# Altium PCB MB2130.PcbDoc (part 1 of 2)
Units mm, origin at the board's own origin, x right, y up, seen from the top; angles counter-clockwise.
Board outline 43 x 51.11 mm, 4 copper layers (Top Layer, Signal Layer 1, Signal Layer 2, Bottom Layer), stack 1.592 mm thick; 94 components, 90 nets, 382 pads, 433 vias.
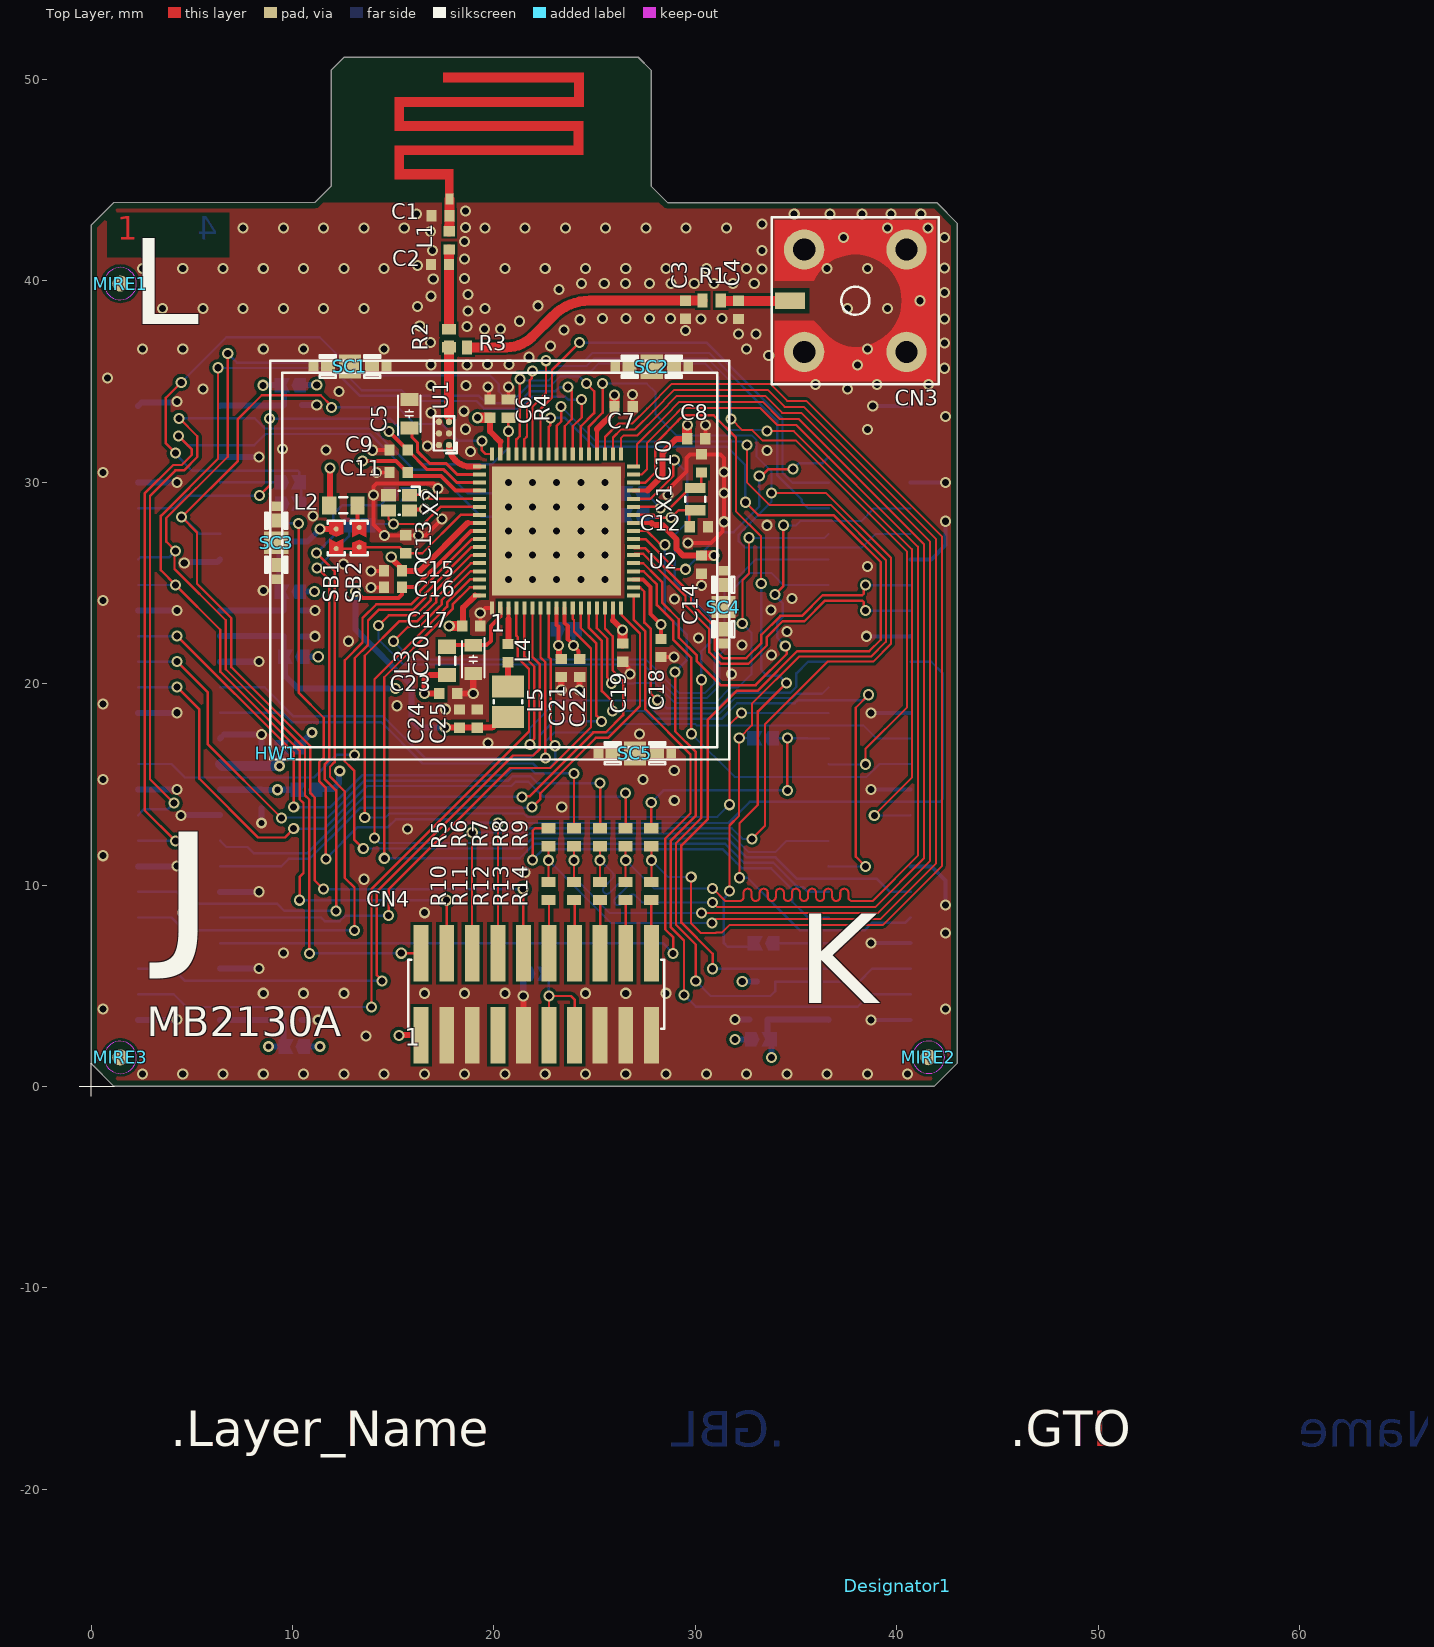
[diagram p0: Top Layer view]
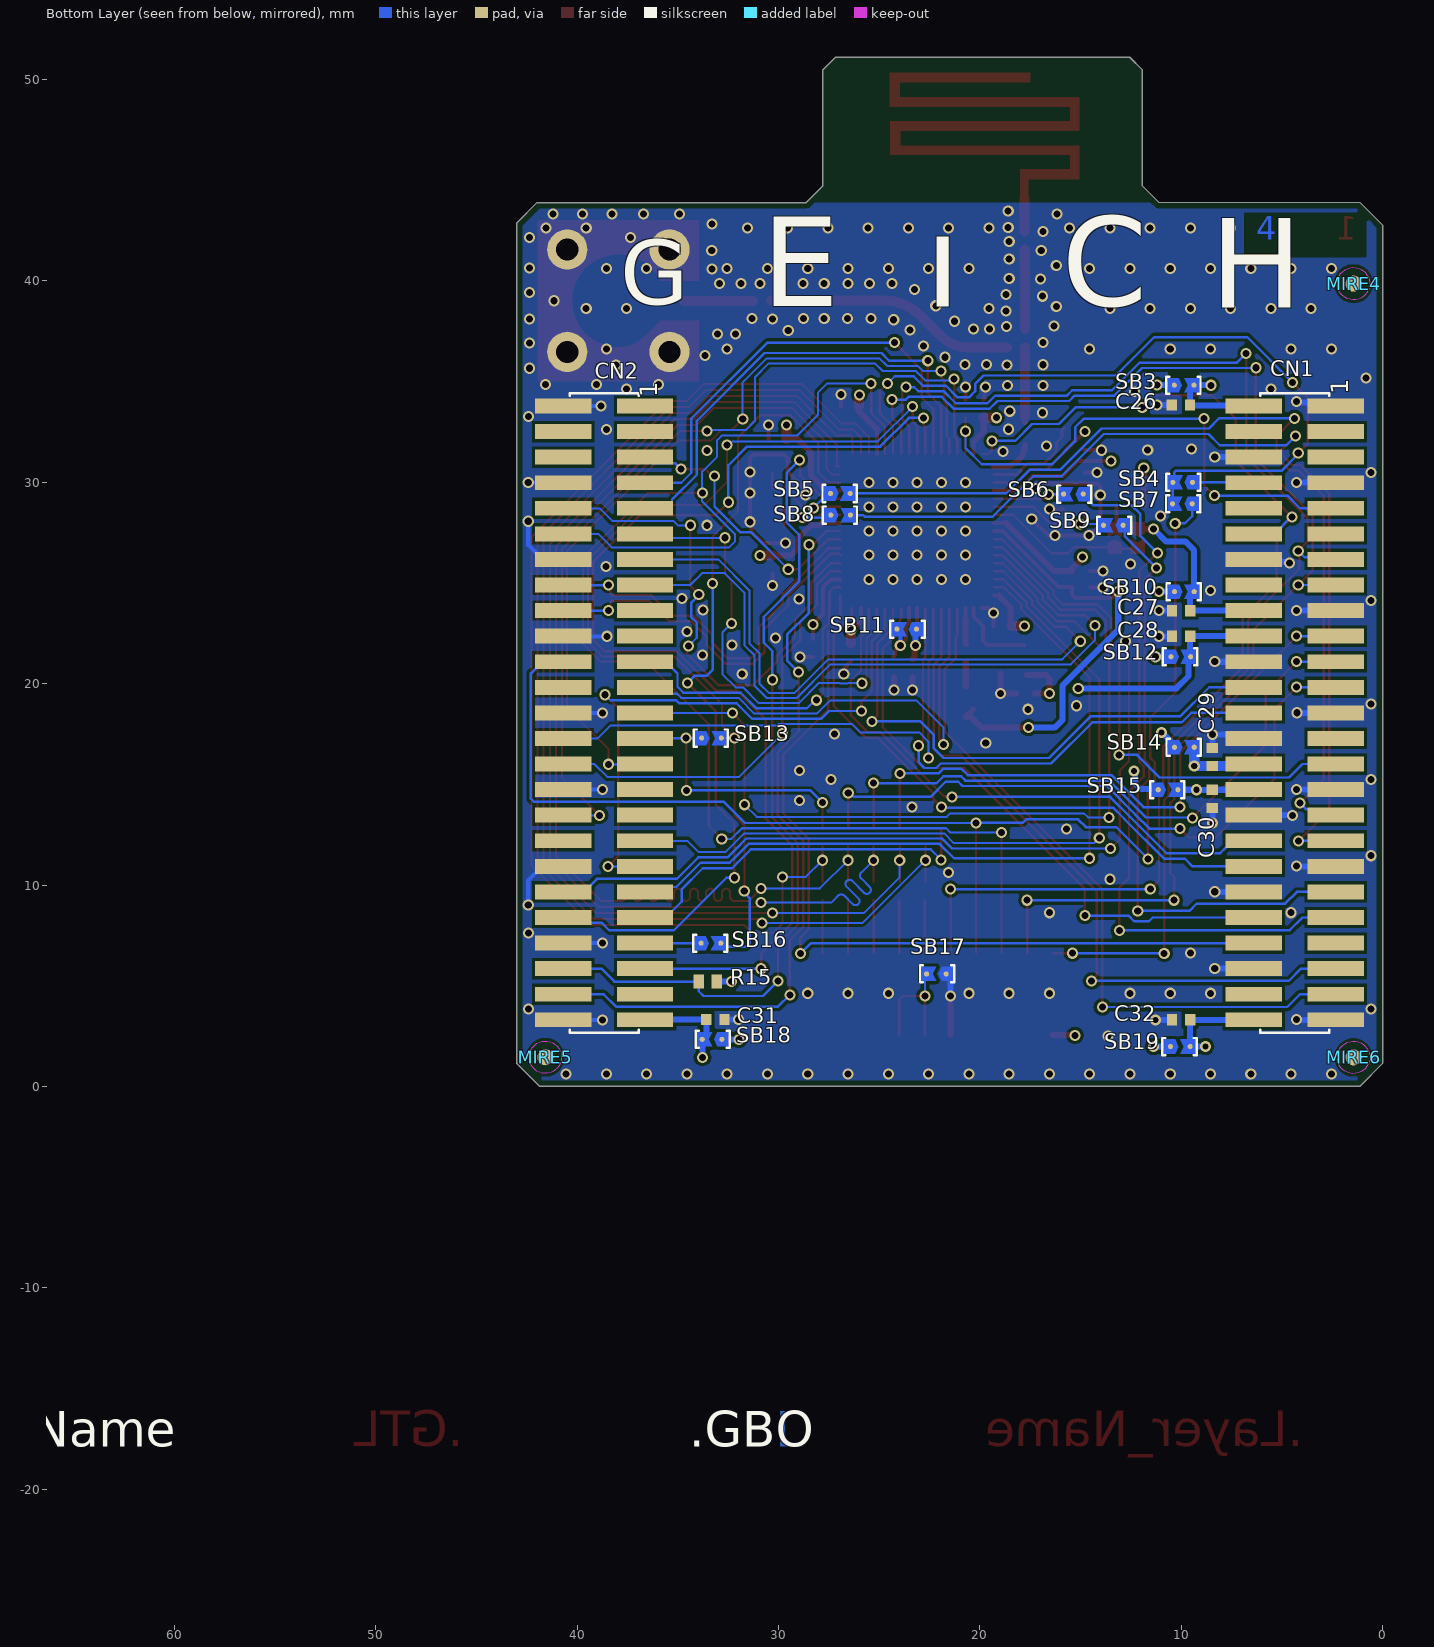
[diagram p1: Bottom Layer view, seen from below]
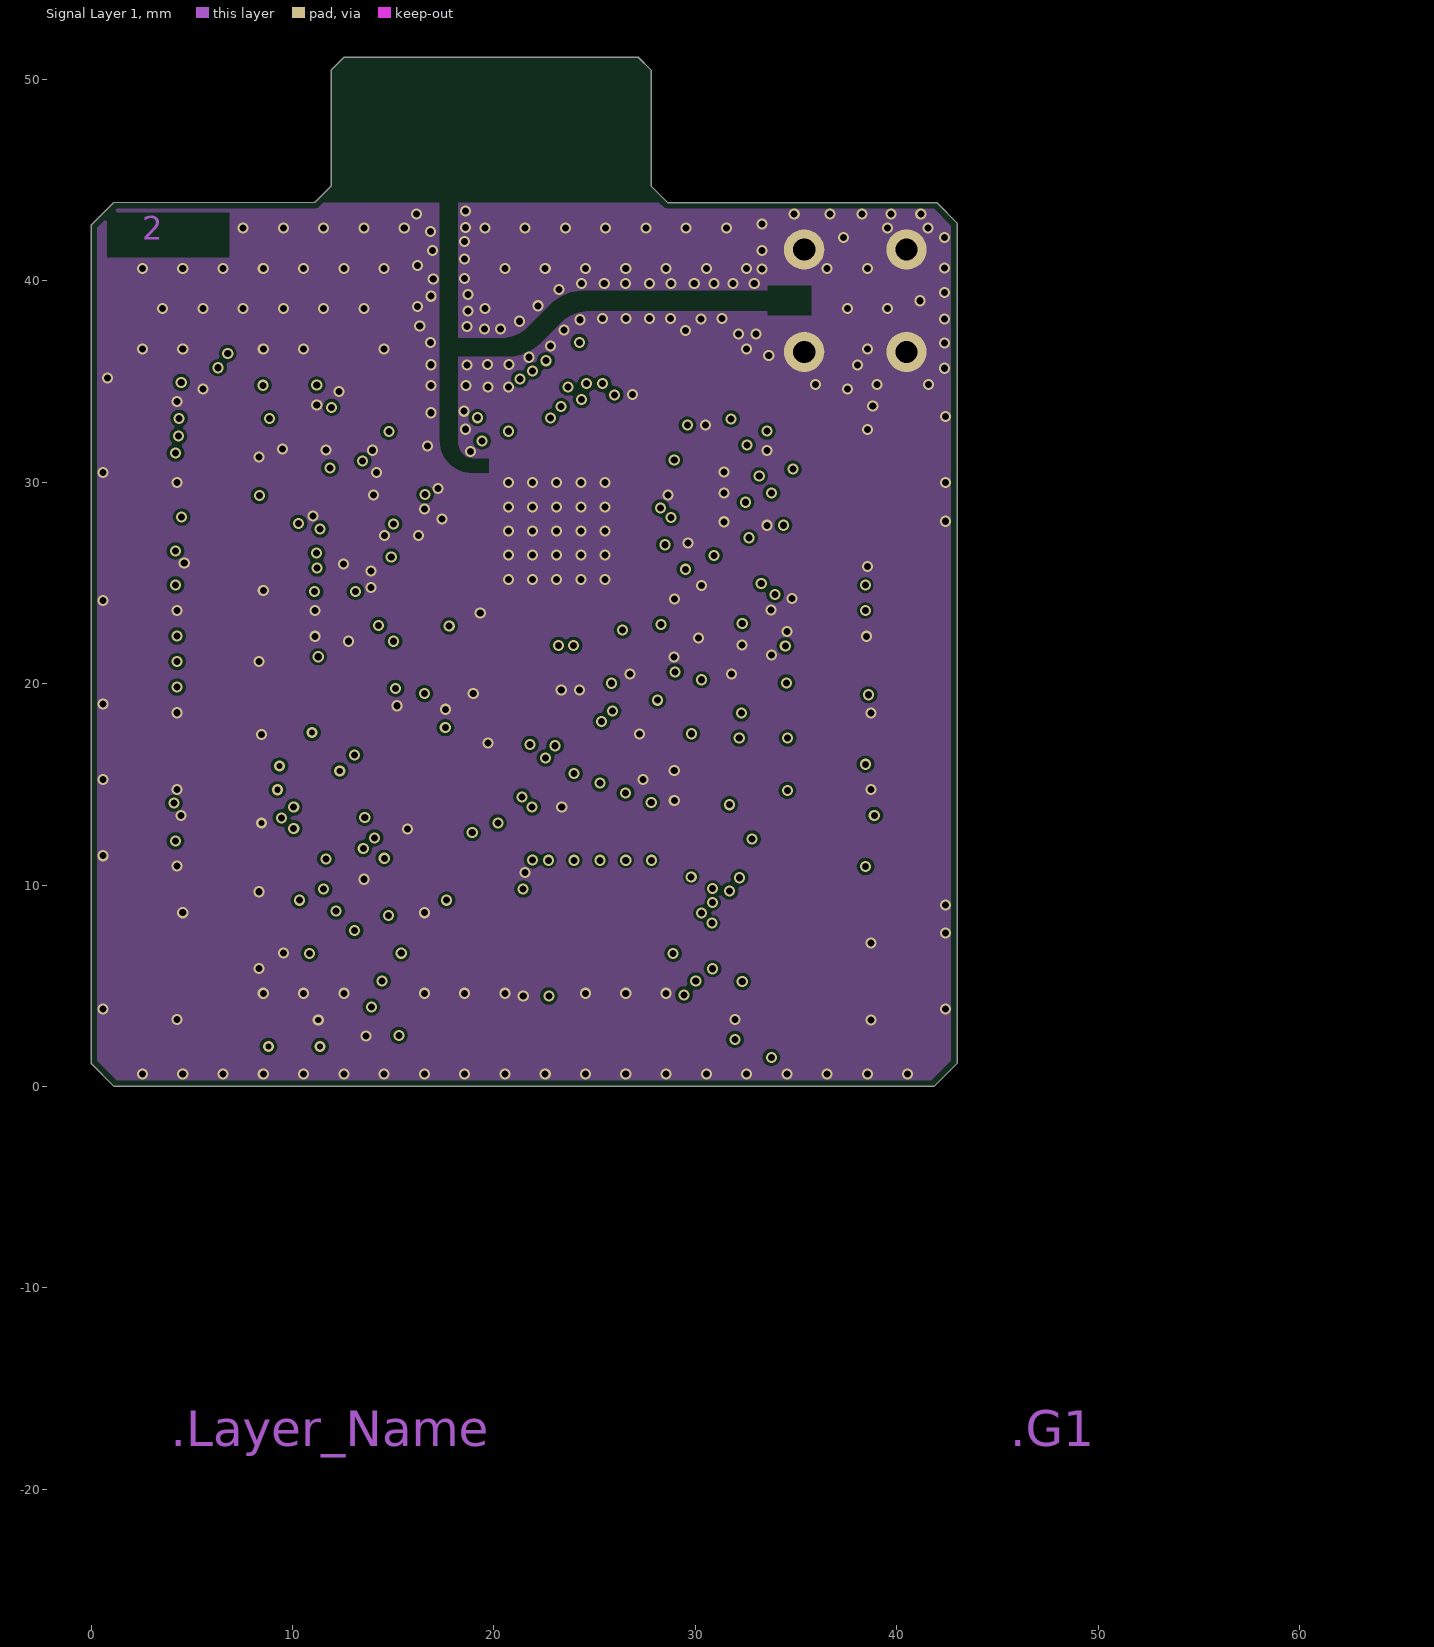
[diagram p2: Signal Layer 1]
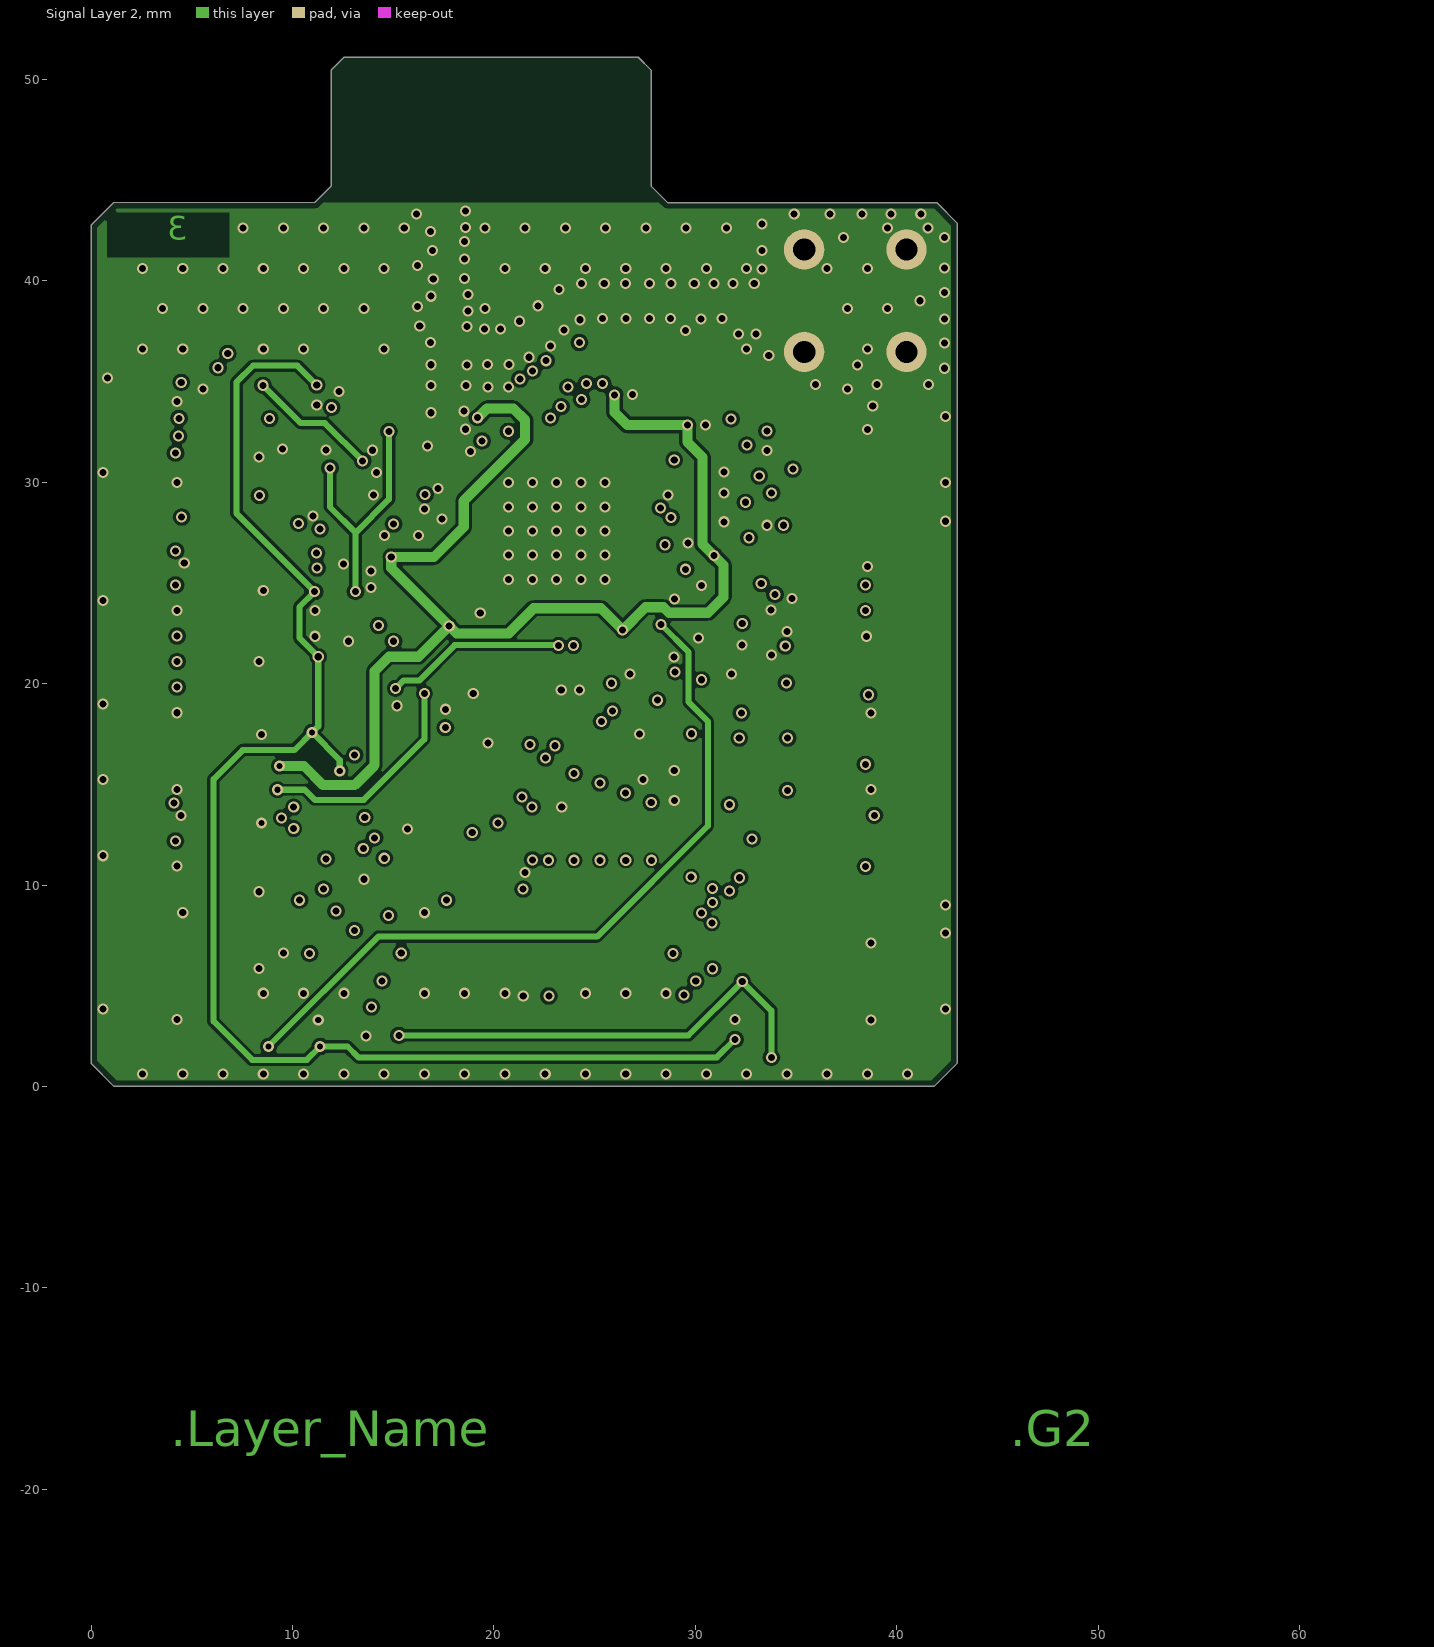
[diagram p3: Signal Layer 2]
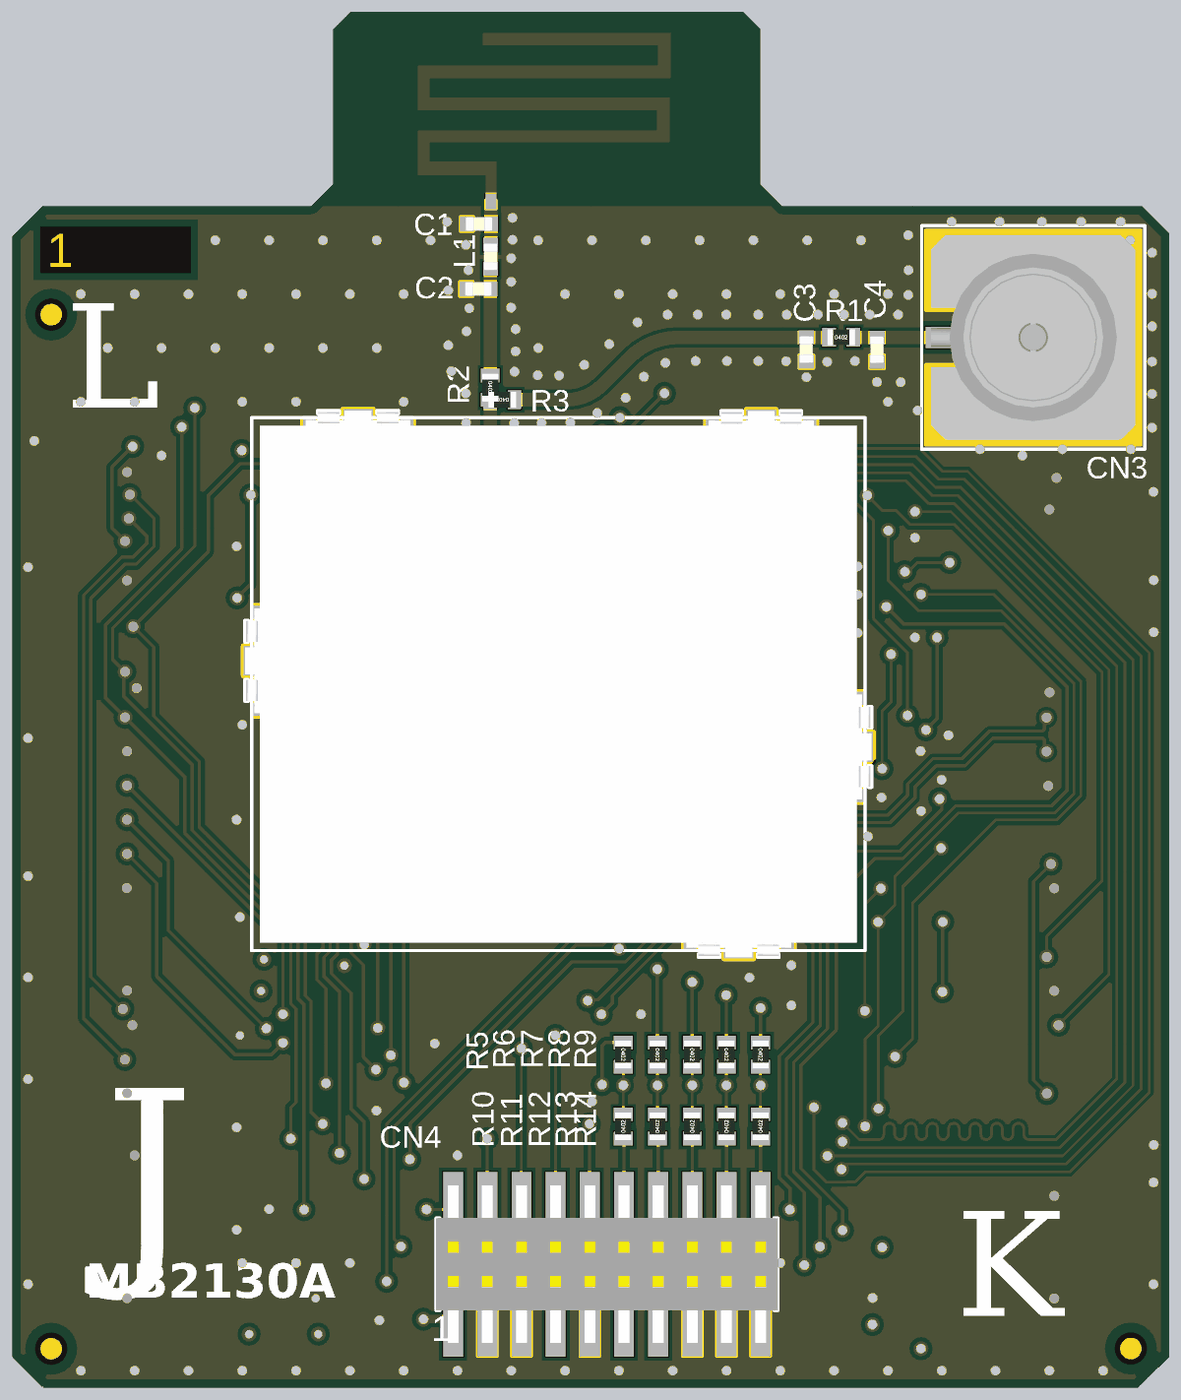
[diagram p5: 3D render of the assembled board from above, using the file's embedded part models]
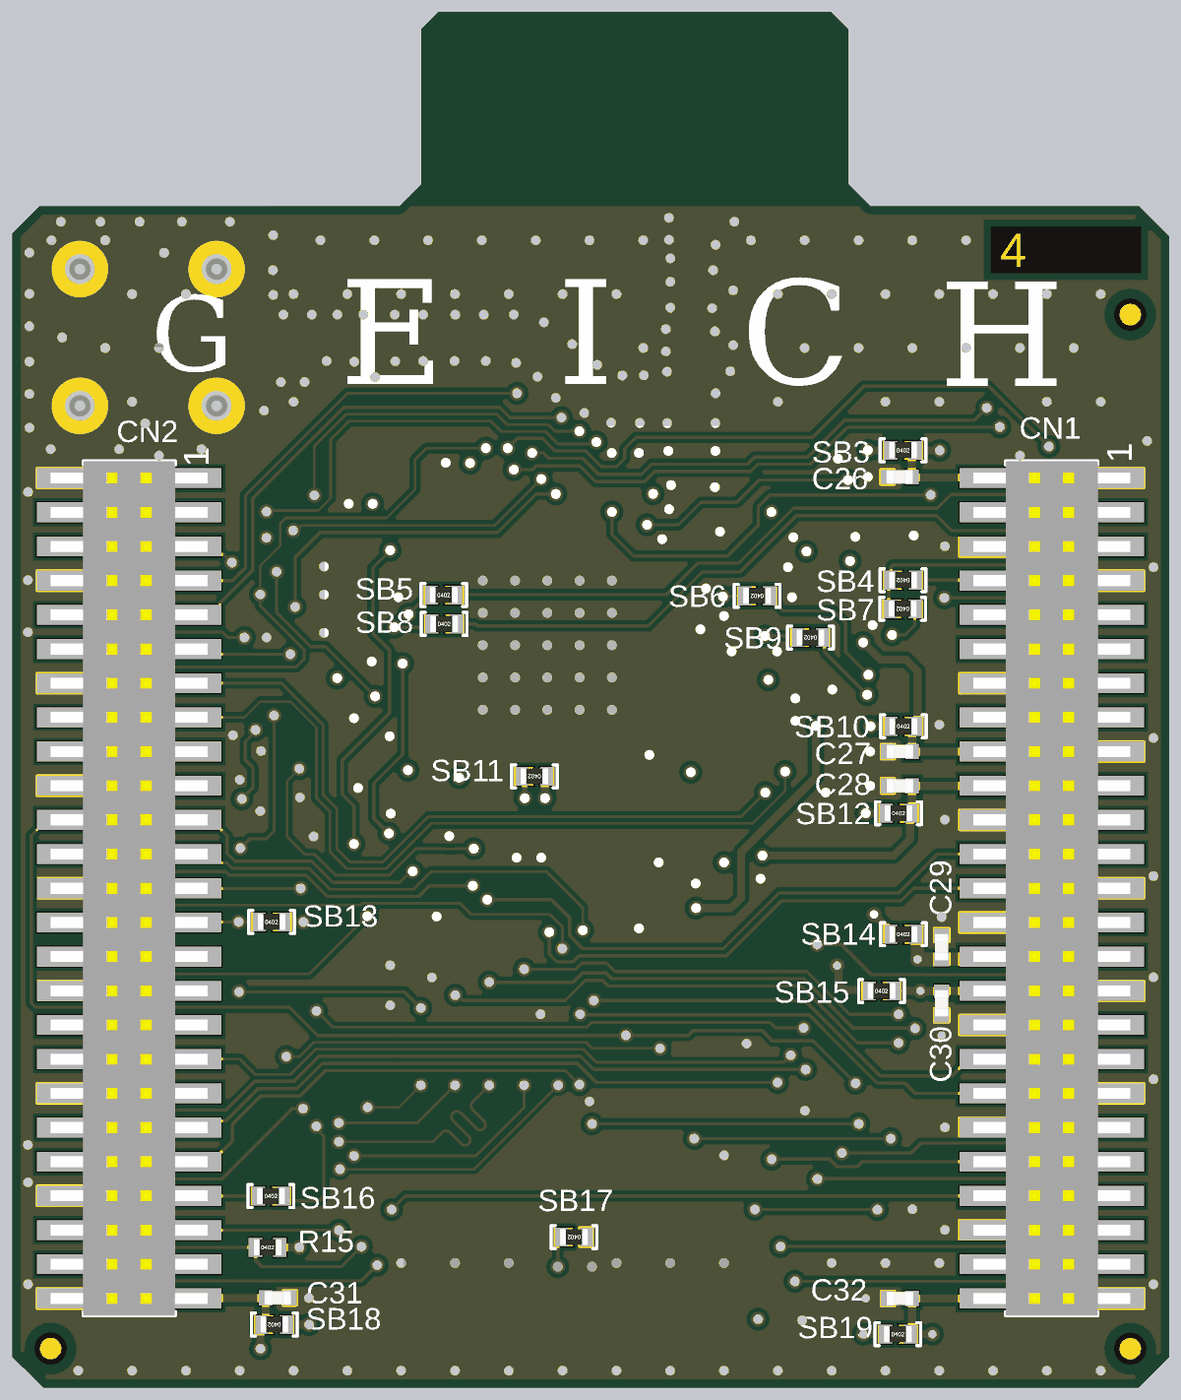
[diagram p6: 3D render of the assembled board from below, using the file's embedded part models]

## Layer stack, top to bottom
Top Solder: solder mask 0.02, Solder Resist, Dk 3.5
Top Layer: signal copper 0.07
Dielectric 1: prepreg 0.076, 1080HR RC68, Dk 4.2
Signal Layer 1: signal copper 0.035
Dielectric 2: core 1.23, FR4, Dk 4.5
Signal Layer 2: signal copper 0.035
Dielectric 3: prepreg 0.076, 1080HR RC68, Dk 4.2
Bottom Layer: signal copper 0.07
Bottom Solder: solder mask 0.02, Solder Resist, Dk 3.5

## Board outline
0,1.139 0,42.769 1.122,43.891 11.106,43.893 11.927,44.713 11.927,50.471 12.562,51.106 27.167,51.106 27.802,50.471 27.802,44.711 28.622,43.891 41.987,43.886 43,42.873 43.001,1.141 41.852,0 1.139,0

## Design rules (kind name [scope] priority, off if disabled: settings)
BoardOutlineClearance [All] p1: gap=0.3 ignorepadtopadclearanceinfootprint=FALSE except(0: Arc-SplitContinuation Track-SplitContinuation SMDPad-SplitContinuation THPad-SplitContinuation Via-SplitContinuation Fill-SplitContinuation Poly-SplitContinuation Region-SplitContinuation Text-SplitContinuation)
Clearance Clearance_DP_GND [InNetClass('DP') vs InNet('GND')] p1: gap=0.12 ignorepadtopadclearanceinfootprint=FALSE
Clearance Clearance_RF-IN_GND [InNet('IPD_in') vs InNet('GND')] p2: gap=0.15 ignorepadtopadclearanceinfootprint=FALSE
Clearance Clearance_SE_GND [InNetClass('S50') vs InNet('GND')] p3: gap=0.12 ignorepadtopadclearanceinfootprint=FALSE
Clearance Clearance_S50 [InNetClass('S50')] p4: gap=0.15 ignorepadtopadclearanceinfootprint=FALSE except(0.2: Arc-Arc Arc-Track Arc-Fill Arc-Poly Arc-Region Track-Track Track-Fill Track-Poly Track-Region)
Clearance [All] p5: gap=0.15 ignorepadtopadclearanceinfootprint=FALSE
ComponentClearance [All] p1: gap=0.2 collisioncheckmode=3 verticalgap=0.2 showdistances=FALSE
DiffPairsRouting [All] p1: maxlimit=0.254 minlimit=0.15 mostfreqgap=0.254 toplayer_maxgap=0.15 toplayer_prefgap=0.15 toplayer_minwidth=0.12 toplayer_maxwidth=0.12 toplayer_prefwidth=0.12 bottomlayer_maxgap=0.15 bottomlayer_prefgap=0.15 bottomlayer_minwidth=0.12 bottomlayer_maxwidth=0.12 bottomlayer_prefwidth=0.12 impedanceprofiledriven=TRUE impedanceprofileid={83C80AEC-0C39-4BC7-B724-3D17928A45DD} impedanceprofilevalue=90.000000 maxuncoupledlength=12.7
HoleSize [All] p1: absolutevalues=TRUE maxlimit=10 minlimit=0.025 maxpercent=80.000 minpercent=20.000
MatchedLengths MatchedLengths_ETM [InNetClass('ETM')] p1: tolerance=3 checknetsindiffpair=FALSE checkdiffpairvsdiffpair=TRUE checkxsignals=TRUE checkothers=TRUE
MinimumSolderMaskSliver [All] p1: minsoldermaskwidth=0.1
PlaneConnect [All] p1: planeconnectstyle=Relief reliefexpansion=0.508 reliefentries=4 reliefconductorwidth=0.21 reliefairgap=0.21
PolygonConnect Path_RF [InNet('NetC12_2')] p1: connectstyle=Direct reliefconductorwidth=0.254 reliefentries=4 polygonreliefangle="90 Angle" airgapwidth=0.254
PolygonConnect PolygonConnect_via [IsVia] p2: connectstyle=Direct reliefconductorwidth=0.254 reliefentries=4 polygonreliefangle="90 Angle" airgapwidth=0.254
PolygonConnect General [All] p3: connectstyle=Direct reliefconductorwidth=0.2 reliefentries=4 polygonreliefangle="90 Angle" airgapwidth=0.2
RoutingVias [All] p1: holewidth=0.3 width=0.8 viastyle="Through Hole" minholewidth=0.2 minwidth=0.5 maxholewidth=3.5 maxwidth=6.5
SilkToSilkClearance [All] p1 off: silktosilkclearance=0.2
SilkToSolderMaskClearance [IsPad] p1 off: minsilkscreentomaskgap=0.2 clearancetoexposedcopper=TRUE
SolderMaskExpansion [All] p1: expansion=0.102 istentingtop=FALSE
Width Width_VDD [InNetClass('VDD')] p1: maxlimit=0.3 minlimit=0.2 preferedwidth=0.3
Width Width_VDD4 [InNet('VDD4')] p2: maxlimit=0.5 minlimit=0.2 preferedwidth=0.5
Width Width_S50 [InNetClass('S50')] p3: maxlimit=0.5 minlimit=0.1 preferedwidth=0.254 toplayer_prefwidth=0.1 bottomlayer_prefwidth=0.1 impedanceprofiledriven=TRUE impedanceprofileid={8D9B8D96-6614-473A-BC45-880F726FB23A} impedanceprofilevalue=50.000000 minimp=50.000000 maximp=50.000000 favimp=50.000000
Width [All] p4: maxlimit=6 minlimit=0.1 preferedwidth=0.12 midlayer1_maxwidth=0.512 midlayer2_maxwidth=0.512 minimp=50.000000 maximp=50.000000 favimp=50.000000
23 further rules are at their usual default settings.

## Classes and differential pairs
net class DP: USB_HS_N USB_HS_P
net class VDD: GND NetSB3_1 VDD1 VDD3 VDD5 VDD14 VDDA VDDUSB
net class ETM: ETM.CLK ETM.D0 ETM.D1 ETM.D2 ETM.D3
net class S50: ant_in ant_path ETM.CLK ETM.D0 ETM.D1 ETM.D2 ETM.D3 IPD_out SMA-path SMA_in
component class U_MCU_Clock&Reset: C10 C12 R4 X1 X2
component class U_External_Debug_Interface: CN4 J1 R10 R11 R12 R13 R14 SB17
component class U_MCU: C26 C27 C28 C29 C30 C31 C32 CN1 CN2 R5 R6 R7 R8 R9 R15 SB3 SB4 SB5 SB6 SB7 SB8 SB9 SB10 SB12 SB13 SB14 SB15 SB16 SB18 SB19
component class U_MCU_Power: ANT1 C1 C2 C3 C4 C5 C6 C7 C8 C9 C11 C13 C14 C15 C16 C17 C18 C19 C20 C21 C22 C23 C24 C25 CN3 HW1 L1 L2 L3 L4 L5 R1 R2 R3 SB1 SB2 SB11 SC1 SC2 SC3 SC4 SC5 U1 U2
differential pair USB: +USB_HS_P -USB_HS_N

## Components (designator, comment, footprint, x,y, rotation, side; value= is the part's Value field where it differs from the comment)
ANT1 "2.4GHz_BT_ANT" ANT_BT_BNRG_2P4GHZ_MB2032 17.649,44.066 r90 top value=2.4GHZ_BNRG_ANT
C1 "Capacitor" C0402 17.348,43.231 r0 top value=1.1pF
C2 "Capacitor" C0402 17.323,40.818 r180 top value=1.5pF
C3 "Capacitor" C0402 29.515,38.567 r90 top value=1.5pF
C4 "Capacitor" C0402 32.14,38.56 r90 top value=1.8pF
C5 "Capacitor" C0603 15.799,33.402 r270 top value=470nF
C6 "Capacitor" C0402 19.807,33.655 r90 top value=100nF
C7 "Capacitor" C0402 26.441,33.757 r0 top value=100nF
C8 "Capacitor" C0402 30.048,32.156 r0 top value=100nF
C9 "Capacitor" C0402 15.265,31.598 r180 top value=100nF
C10 "Capacitor" C0402 30.302,30.937 r270 top value=6pF
C11 "Capacitor" C0402 15.265,30.48 r180 top value=100nF
C12 "Capacitor" C0402 30.175,27.788 r180 top value=6pF
C13 "Capacitor" C0402 15.621,26.924 r90 top value=100nF
C14 "Capacitor" C0402 30.302,25.908 r270 top value=100nF
C15 "Capacitor" C0402 14.986,25.603 r180 top value=100nF
C16 "Capacitor" C0402 14.986,24.79 r0 top value=100nF
C17 "Capacitor" C0402 18.872,22.86 r0 top value=100nF
C18 "Capacitor" C0402 28.296,21.768 r270 top value=100nF
C19 "Capacitor" C0402 26.391,21.539 r270 top value=100nF
C20 "Capacitor" C0603 18.974,21.209 r90 top value=10uF
C21 "Capacitor" C0402 23.343,20.777 r90 top value=1uF
C22 "Capacitor" C0402 24.257,20.777 r90 top value=1uF
C23 "Capacitor" C0402 17.729,19.507 r0 top value=1uF
C24 "Capacitor" C0402 18.288,18.263 r90 top value=2.2uF
C25 "Capacitor" C0402 19.177,18.263 r270 top value=4.7uF
C26 "Capacitor" C0402 10.019,33.832 r180 bottom value=1uF
C27 "Capacitor" C0402 10.007,23.627 r180 bottom value=1uF
C28 "Capacitor" C0402 10.008,22.352 r180 bottom value=1uF
C29 "Capacitor" C0402 8.458,16.358 r270 bottom value=1uF
C30 "Capacitor" C0402 8.458,14.275 r90 bottom value=1uF
C31 "Capacitor" C0402 33.135,3.327 r0 bottom value=1uF
C32 "Capacitor" C0402 10.008,3.306 r180 bottom value=1uF
CN1 "FTSH-125-02-L-DV" CON_SAMTEC_FTSH-125-02-L-DV_INV 4.366,18.548 r270 bottom locked value="Header 25x2"
CN2 "FTSH-125-02-L-DV" CON_SAMTEC_FTSH-125-02-L-DV_INV 38.656,18.548 r270 bottom locked value="Header 25x2"
CN3 "SMA-J-P-H-ST-EM1" CON_ROSENBERGER_32K141_40ML5 37.948,39.014 r270 top value=32K141-40ML5
CN4 "Header 10x2" CON_SAMTEC_FTSH-110-01-L-DV 22.101,4.579 r0 top
Designator1 "Comment" Sheetbox_4L2S -5.049,-30.142 r0 top
HW1 "RF Shield (22.2x19.2x2mm)" SHIELD_RF_ST-CUSTOM_22P2X19P2_H2 9.195,16.535 r0 top locked
L1 "Inductor" C0402 17.78,42.012 r90 top value=1.5nH
L2 "BEAD" IND_0603_H0P8 12.522,28.854 r180 top value="47R @ 100MHz"
L3 "BEAD" IND_0603_H0P8 17.678,21.133 r270 top value="47R @ 100MHz"
L4 "Inductor" C0402 20.701,21.514 r270 top value=10nH
L5 "Inductor" L0805_H0P9 20.701,19.101 r270 top value=2.2uH
MIRE1 "Comment" MIRE_PLACE_SMD_0P8MM 1.446,39.863 r0 top
MIRE2 "Comment" MIRE_PLACE_SMD_0P8MM 41.576,1.448 r0 top
MIRE3 "Comment" MIRE_PLACE_SMD_0P8MM 1.446,1.441 r0 top
MIRE4 "Comment" MIRE_PLACE_SMD_0P8MM 1.446,39.863 r180 bottom
MIRE5 "Comment" MIRE_PLACE_SMD_0P8MM 41.576,1.448 r180 bottom
MIRE6 "Comment" MIRE_PLACE_SMD_0P8MM 1.446,1.441 r180 bottom
"PCB SPEC1" "Comment" PCB_SPECIFICATIONS -2.994,71.413 r0 top
R1 "Resistor" R0402 30.81,39.024 r0 top value=0R
R2 "Resistor" R0402 17.765,37.151 r270 top value=0R
R3 "Resistor" R0402 18.215,36.701 r180 top value=0R
R4 "Resistor" R0402 20.722,33.655 r90 top value=100K
R5 "Resistor" R0402 22.708,12.37 r270 top value=0R
R6 "Resistor" R0402 23.978,12.37 r270 top value=0R
R7 "Resistor" R0402 25.273,12.37 r270 top value=0R
R8 "Resistor" R0402 26.543,12.37 r270 top value=0R
R9 "Resistor" R0402 27.813,12.37 r270 top value=0R
R10 "Resistor" R0402 22.708,9.703 r90 top value=0R
R11 "Resistor" R0402 23.978,9.703 r90 top value=0R
R12 "Resistor" R0402 25.273,9.703 r90 top value=0R
R13 "Resistor" R0402 26.543,9.703 r90 top value=0R
R14 "Resistor" R0402 27.813,9.703 r90 top value=0R
R15 "Resistor" R0402 33.51,5.207 r180 bottom value=100K
SB1 "SB_ON" SOLDER-BRIDGE_R0402-0R 12.167,27.229 r270 top
SB2 "SB_ON" SOLDER-BRIDGE_R0402-0R 13.31,27.229 r90 top
SB3 "SB_ON" SOLDER-BRIDGE_R0402-0R 9.892,34.823 r180 bottom
SB4 "SB_ON" SOLDER-BRIDGE_R0402-0R 9.892,29.997 r0 bottom
SB5 "SB_ON" SOLDER-BRIDGE_R0402-0R 26.964,29.442 r180 bottom
SB6 "SB_ON" SOLDER-BRIDGE_R0402-0R 15.316,29.413 r0 bottom
SB7 "SB_ON" SOLDER-BRIDGE_R0402-0R 9.906,28.931 r0 bottom
SB8 "SB_ON" SOLDER-BRIDGE_R0402-0R 26.949,28.372 r180 bottom
SB9 "SB_ON" SOLDER-BRIDGE_R0402-0R 13.335,27.864 r0 bottom
SB10 "SB_ON" SOLDER-BRIDGE_R0402-0R 9.88,24.567 r180 bottom
SB11 "SB_ON" SOLDER-BRIDGE_R0402-0R 23.597,22.708 r0 bottom
SB12 "SB_ON" SOLDER-BRIDGE_R0402-0R 10.058,21.336 r180 bottom
SB13 "SB_ON" SOLDER-BRIDGE_R0402-0R 33.363,17.297 r180 bottom
SB14 "SB_ON" SOLDER-BRIDGE_R0402-0R 9.881,16.84 r180 bottom
SB15 "SB_ON" SOLDER-BRIDGE_R0402-0R 10.693,14.732 r180 bottom
SB16 "SB_ON" SOLDER-BRIDGE_R0402-0R 33.389,7.112 r180 bottom
SB17 "SB_ON" SOLDER-BRIDGE_R0402-0R 22.123,5.588 r0 bottom
SB18 "SB_ON" SOLDER-BRIDGE_R0402-0R 33.262,2.337 r0 bottom
SB19 "SB_ON" SOLDER-BRIDGE_R0402-0R 10.084,1.981 r180 bottom
SC1 "Shield-clip_S0951-46R" CLIP_HARWIN_S0951-46R 12.852,35.75 r180 top value=S0951-46R
SC2 "Shield-clip_S0951-46R" CLIP_HARWIN_S0951-46R 27.838,35.738 r180 top value=S0951-46R
SC3 "Shield-clip_S0951-46R" CLIP_HARWIN_S0951-46R 9.195,27 r90 top value=S0951-46R
SC4 "Shield-clip_S0951-46R" CLIP_HARWIN_S0951-46R 31.394,23.8 r90 top value=S0951-46R
SC5 "Shield-clip_S0951-46R" CLIP_HARWIN_S0951-46R 27,16.535 r180 top value=S0951-46R
U1 "MLPF-WB-04D3" ICC_CSPG_6BUMPS_1X1P60_P050-P0577 17.519,32.426 r180 top
U2 "STM32WBA65RI" ICC_VFQFPN68-EPAD_8X8_P040 23.114,27.58 r90 top value=STM32WBA65RIV7
X1 "XTAL_2_PINS" CRY_NX1610SE_2P 29.997,29.159 r270 top value=32.768kHz
X2 "XTAL_4_PINS" CRY_NX1612SA_4P 15.291,28.981 r180 top value=32MHz

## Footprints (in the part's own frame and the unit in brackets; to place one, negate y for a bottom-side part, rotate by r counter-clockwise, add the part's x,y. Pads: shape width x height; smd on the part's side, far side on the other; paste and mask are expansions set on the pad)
ANT_BT_BNRG_2P4GHZ_MB2032 [mm] "MCD-03495"
  rect 0.56x0.4 smd mask+0.05: 1(0,-0.14)
  Top Layer region: 4.585,-6.816 4.585,2.134 3.86,2.134 3.86,-6.791 2.21,-6.791 2.21,2.134 1.485,2.134 1.485,-0.341 -0.14,-0.341 -0.165,-0.341 -0.165,0.059 0.985,0.059 0.985,2.584 2.61,2.584 2.635,2.584 2.635,-6.316 3.01,-6.316 3.385,-6.316 3.385,2.584 5.01,2.584 5.06,2.584 5.06,-6.341 5.81,-6.341 5.81,0.159 6.26,0.159 6.26,-6.816
  body extent 1.11,-0.88 1.75,-0.54, height 0.33
C0402 [mm]
  rect 0.51x0.56 smd mask+0.05: 1(-0.45,0) 2(0.45,0)
  body extent -0.5,-0.3 0.5,0.3, height 0.4
C0603 [mm]
  rect 0.64x0.89 smd mask+0.05: 1(-0.7,0) 2(0.7,0)
  silkscreen extent -0.9,-0.55 1.05,0.55, body extent -0.9,-0.5 0.9,0.5, height 1.4
CLIP_HARWIN_S0951-46R [mm] "MCD-01587_CLIP-X1"
  rect 0.48x0.5 smd mask+0.1: 1(-1.81,0) 1(1.81,0)
  rect 0.7x0.5 smd mask+0.1: 1(-1.1,0) 1(1.1,0)
  rect 1.1x1.2 smd mask+0.1: 1(0,0)
  silkscreen extent -1.5,-0.55 1.5,0.55, body extent -2.05,-0.65 2.05,0.65, height 1.28
CON_ROSENBERGER_32K141_40ML5 [mm] "MCD-03951"
  rect 0.8x1.5 smd mask+0.05: 1(0,-3.25)
  round 2 hole 1.1 mask+0.05: 2(-2.54,-2.54) 3(-2.54,2.54) 4(2.54,2.54) 5(2.54,-2.54)
  Top Layer region: -1,-4 -1,-2.071 -1,-2.071 -1,-2.071 -1,-2.071 -1.8,-1.432 -2.243,-0.51 -2.242,0.513 -1.798,1.435 -0.998,2.072 0,2.3 0,2.3 0.88,2.125 1.626,1.626 2.125,0.88 2.3,0 2.3,0 2.158,-0.713 1.755,-1.317 1.755,-1.317 1,-2.071 1,-4 4,-4 4,4 -4,4 -4,-4
  silkscreen extent -4.15,-4.15 4.15,4.15, body extent -3.8,-3.8 3.8,3.8, height 8.76
CON_SAMTEC_FTSH-110-01-L-DV [mm]
  rect 0.74x2.79 smd mask+0.05: 1(-5.715,-2.035) 2(-5.715,2.035) 3(-4.445,-2.035) 4(-4.445,2.035) 5(-3.175,-2.035) 6(-3.175,2.035) 7(-1.905,-2.035) 8(-1.905,2.035) 9(-0.635,-2.035) 10(-0.635,2.035) 11(0.635,-2.035) 12(0.635,2.035) 13(1.905,-2.035) 14(1.905,2.035) 15(3.175,-2.035) 16(3.175,2.035) 17(4.445,-2.035) 18(4.445,2.035) 19(5.715,-2.035) 20(5.715,2.035)
  silkscreen extent -6.35,-1.71 6.35,1.71, body extent -6.35,-2.92 6.35,2.92, height 5.97
CON_SAMTEC_FTSH-125-02-L-DV_INV [mm]
  rect 0.74x2.79 smd mask+0.05: 1(-15.24,2.035) 2(-15.24,-2.035) 3(-13.97,2.035) 4(-13.97,-2.035) 5(-12.7,2.035) 6(-12.7,-2.035) 7(-11.43,2.035) 8(-11.43,-2.035) 9(-10.16,2.035) 10(-10.16,-2.035) 11(-8.89,2.035) 12(-8.89,-2.035) 13(-7.62,2.035) 14(-7.62,-2.035) 15(-6.35,2.035) 16(-6.35,-2.035) 17(-5.08,2.035) 18(-5.08,-2.035) 19(-3.81,2.035) 20(-3.81,-2.035) 21(-2.54,2.035) 22(-2.54,-2.035) 23(-1.27,2.035) 24(-1.27,-2.035) 25(0,2.035) 26(0,-2.035) 27(1.27,2.035) 28(1.27,-2.035) 29(2.54,2.035) 30(2.54,-2.035) 31(3.81,2.035) 32(3.81,-2.035) 33(5.08,2.035) 34(5.08,-2.035) 35(6.35,2.035) 36(6.35,-2.035) 37(7.62,2.035) 38(7.62,-2.035) 39(8.89,2.035) 40(8.89,-2.035) 41(10.16,2.035) 42(10.16,-2.035) 43(11.43,2.035) 44(11.43,-2.035) 45(12.7,2.035) 46(12.7,-2.035) 47(13.97,2.035) 48(13.97,-2.035) 49(15.24,2.035) 50(15.24,-2.035)
  silkscreen extent -15.88,-1.71 15.88,1.71, body extent -15.87,-2.92 15.88,2.92, height 4.82
CRY_NX1610SE_2P [mm] "MCD-02291"
  rect 0.5x1 smd mask+0.05: 1(-0.55,0) 2(0.55,0)
  silkscreen extent -0.13,-0.5 0.13,0.5, body extent -0.8,-0.5 0.8,0.5, height 0.45
CRY_NX1612SA_4P [mm] "MCD-02262"
  rect 0.75x0.6 smd mask+0.038: 1(-0.525,-0.375) 2(0.525,-0.375) 3(0.525,0.375) 4(-0.525,0.375)
  silkscreen extent -1.02,-0.8 0.03,0.6, body extent -0.8,-0.6 0.8,0.6, height 0.31
ICC_CSPG_6BUMPS_1X1P60_P050-P0577 [mm] "MCD-03490"
  round 0.32 smd paste-2539.97 mask-0.05: A1(-0.25,0.577) A2(-0.25,0) A3(-0.25,-0.577) B1(0.25,0.577) B2(0.25,0) B3(0.25,-0.577)
  silkscreen extent -0.64,-0.85 0.51,0.97, body extent -0.51,-0.81 0.51,0.81, height 0.7
ICC_VFQFPN68-EPAD_8X8_P040 [mm] "MCD-03837"
  rect 0.65x0.2 smd mask+0.05: 1(-3.825,3.2) 2(-3.825,2.8) 3(-3.825,2.4) 4(-3.825,2) 5(-3.825,1.6) 6(-3.825,1.2) 7(-3.825,0.8) 8(-3.825,0.4) 9(-3.825,0) 10(-3.825,-0.4) 11(-3.825,-0.8) 12(-3.825,-1.2) 13(-3.825,-1.6) 14(-3.825,-2) 15(-3.825,-2.4) 16(-3.825,-2.8) 17(-3.825,-3.2) 35(3.825,-3.2) 36(3.825,-2.8) 37(3.825,-2.4) 38(3.825,-2) 39(3.825,-1.6) 40(3.825,-1.2) 41(3.825,-0.8) 42(3.825,-0.4) 43(3.825,0) 44(3.825,0.4) 45(3.825,0.8) 46(3.825,1.2) 47(3.825,1.6) 48(3.825,2) 49(3.825,2.4) 50(3.825,2.8) 51(3.825,3.2)
  rect 0.2x0.65 smd mask+0.05: 18(-3.2,-3.825) 19(-2.8,-3.825) 20(-2.4,-3.825) 21(-2,-3.825) 22(-1.6,-3.825) 23(-1.2,-3.825) 24(-0.8,-3.825) 25(-0.4,-3.825) 26(0,-3.825) 27(0.4,-3.825) 28(0.8,-3.825) 29(1.2,-3.825) 30(1.6,-3.825) 31(2,-3.825) 32(2.4,-3.825) 33(2.8,-3.825) 34(3.2,-3.825) 52(3.2,3.825) 53(2.8,3.825) 54(2.4,3.825) 55(2,3.825) 56(1.6,3.825) 57(1.2,3.825) 58(0.8,3.825) 59(0.4,3.825) 60(0,3.825) 61(-0.4,3.825) 62(-0.8,3.825) 63(-1.2,3.825) 64(-1.6,3.825) 65(-2,3.825) 66(-2.4,3.825) 67(-2.8,3.825) 68(-3.2,3.825)
  rect 6.4x6.4 smd mask+0.05: 69(0,0)
  body extent -4.08,-4.08 4.08,4.08, height 1.1
IND_0603_H0P8 [mm]
  rect 0.7x0.9 smd mask+0.05: 1(-0.7,0) 2(0.7,0)
  silkscreen extent -0.2,-0.4 0.2,0.4, body extent -0.8,-0.4 0.8,0.4, height 0.8
L0805_H0P9 [mm]
  rect 1.1x1.6 smd mask+0.05: 1(-0.75,0) 2(0.75,0)
  silkscreen extent -0.08,-0.7 0.08,0.7, body extent -1.07,-0.7 1.07,0.7, height 1.2
MIRE_PLACE_SMD_0P8MM [mm]
  round 0.8 smd paste-10 mask+0.2: 1(0,0)
  Top Layer keep-out circle w0.01: c0,0 r0.804
PCB_SPECIFICATIONS [mm]
R0402 [mm]
  rect 0.51x0.7 smd mask+0.05: 1(-0.45,0) 2(0.45,0)
  body extent -0.52,-0.3 0.52,0.3, height 0.4
Sheetbox_4L2S [mil] "Sheetbox 4 layers / 2 silkscreens"
  round 20 on Mech16: 1(813.78,210.69) 1(2736.9,210.69)
SHIELD_RF_ST-CUSTOM_22P2X19P2_H2 [mm] "MCD-02088"
  silkscreen extent -0.3,-0.3 22.5,19.5, body extent 0,0 22.2,19.2, height 2.45
SOLDER-BRIDGE_R0402-0R [mil] "MCD-01619"
  round 10 smd paste-393.7: 1(-17.72,0) 2(20.67,0)
  Top Layer region: -30.51,-13.78 -30.51,13.78 -8.86,13.78 -2.95,0 -8.86,-13.78
  Top Layer region: 1.48,13.78 8.37,0 1.48,-13.78 30.51,-13.78 30.51,13.78
  silkscreen extent -33,-17 33,17, body extent -20,-12 20,12, height 14

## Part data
ANT1: library part MCD-03495, "2.4 GHZ Bluetooth BNRG PCB antenna", Manufacturer=N/A
C1: library part MCD-03940, "Capacitor, MLCC, 1.1pF, 50V, C0G, +/-0.05pF, 0402, T=0.5mm", Manufacturer=MURATA, Manufacturer_Part_Number=GJM1555C1H1R1WB01, Package=0402
C2 C3: library part MCD-02994, "Capacitor, MLCC, 1.5pF, 50V, C0G, +/-0.25pF, 0402, T=0.5mm", Manufacturer=MURATA, Manufacturer_Part_Number=GRM1555C1H1R5CA01, Package=0402
C4: library part MCD-02995, "Capacitor, MLCC, 1.8pF, 50V, C0G, +/-0.25pF, 0402, T=0.5mm", Manufacturer=MURATA, Manufacturer_Part_Number=GRM1555C1H1R8CA01, Package=0402
C5: library part MCD-01006, "Capacitor, MLCC, 470nF, 16V, X7R, +/-10%, 0603, T=0.8mm", Manufacturer=YAGEO, Manufacturer_Part_Number=CC0603KRX7R7BB474, Package=0603
C6 C7 C8 C9 C11 C13 C14 C15 C16 C17 C18 C19: library part MCD-00006, "Capacitor, MLCC, 100nF, 16V, X7R, +/-10%, 0402, T=0.5mm", Alternate_Manufacturer=MURATA, Alternate_Manufacturer_Part_Number=GCM155R71C104KA55D, Manufacturer=YAGEO, Manufacturer_Part_Number=CC0402KRX7R7BB104, Package=C0402
C10 C12: library part MCD-03185, "Capacitor, MLCC, 6pF, 50V, NPO, +/-0,25pF, 0402, T=0.5mm", Manufacturer=MURATA, Manufacturer_Part_Number=GJM1555C1H6R0CB01, Package=0402
C20: library part MCD-00243, "Capacitor, MLCC, 10uF, 6V3, X5R, +/-10%, 0603, T=0.8mm", Alternate_Manufacturer=N/A, Manufacturer=YAGEO, Manufacturer_Part_Number=CC0603KRX5R5BB106, Package=0603
C21 C22 C23 C26 C27 C28 C29 C30 C31 C32: library part MCD-01722, "Capacitor, MLCC, 1uF, 10V, X5R, +/-10%, 0402, T=0.5mm", Manufacturer=YAGEO, Manufacturer_Part_Number=CC0402KRX5R6BB105, Package=0402
C24: library part MCD-01823, "Capacitor, MLCC, 2.2uF, 6V3, X5R,+/-10%, 0402, T=0.5mm", Manufacturer=MURATA, Manufacturer_Part_Number=GRM155R60J225KE95D, Package=0402
C25: library part MCD-01356, "Capacitor, MLCC, 4.7uF, 6V3, X5R, +/-20%, 0402, T=0.5mm", Manufacturer=MURATA, Manufacturer_Part_Number=GRM155R60J475ME47, Package=0402
CN1 CN2: library part MCD-02746, "Header, 25x2, 12.7mm, VR, SMD, T=4.83mm", Manufacturer=SAMTEC
CN3: library part MCD-03951, "Straight Jack PCB SMA connector", Manufacturer=ROSENBERGER, Manufacturer_Part_Number=32K141-40ML5, Package="PC-Board SMD Pin-in-Paste (-40M)"
CN4: library part MCD-00557, "Header, 10x2, 1.27mm, VR, SMD, T=3.05mm", Manufacturer=SAMTEC, Manufacturer_Part_Number=FTSH-110-01-L-DV
Designator1 "PCB SPEC1": library part MCD-00279
HW1: library part MCD-03256, Manufacturer=TBD
L1: library part MCD-04157, "Inductor, 1.5nH, +/-0.3nH, 1A, 100mR, 0402, T=0.5mm", Manufacturer=MURATA, Manufacturer_Part_Number=LQG15HS1N5S02D, Package=0402
L2 L3: library part MCD-04370, "Ferrite bead, 47R @100MHz, 500mA, 100mR, 0603, T=0.8mm", Manufacturer="WURTH ELEKTRONIK", Manufacturer_Part_Number=742792608, Package=0603
L4: library part MCD-03035, "Inductor, 10nH, +/-2%, 0.5A, 260mR, 0402, T=0.5mm", Manufacturer=MURATA, Manufacturer_Part_Number=LQG15HS10NJ02D, Package=0402
L5: library part MCD-01060, "Inductor, 2.2uH, +/-20%, 0.7A, 0R156, 0805, T=0.9mm", Manufacturer=MURATA, Manufacturer_Part_Number=LQM21PN2R2MGH, Package=0805
R1 R2 R3 R5 R6 R7 R8 R9 R10 R11 R12 R13 R14: library part MCD-00052, "Resistor, 0R, 0402, +/-5%, 1/16W", Manufacturer=YAGEO, Manufacturer_Part_Number=RC0402JR-070RL, Package=0402
R4 R15: library part MCD-00059, "Resistor, 100K, 0402, +/-1%, 1/16W", Manufacturer=YAGEO, Manufacturer_Part_Number=RC0402FR-07100KL, Package=0402
SB1 SB2 SB3 SB4 SB5 SB6 SB7 SB8 SB9 SB10 SB11 SB12 SB13 SB14 SB15 SB16 SB17 SB18 SB19: library part MCD-01618, "Solder Bridge 0402 ON", Manufacturer=YAGEO, Manufacturer_Part_Number=RC0402JR-070RL, Package=SB0402
SC1 SC2 SC3 SC4 SC5: library part MCD-01587, "shield clip Harwin S0951-46R to fix RF shielded cavity", Manufacturer=HARWIN, Manufacturer_Part_Number=S0951-46R
U1: library part MCD-03521, "IC, 2.4 GHz low pass filter matched to WBA mini board", Manufacturer=STMICROELECTRONICS, Package=CSP
U2: library part MCD-03837, "MCU, ARM Cortex-M33, 2MB Flash, KB SRAM, Crypto, RF 2.4GHz, BLE, 802.15.4", Manufacturer=STMICROELECTRONICS, Manufacturer_Part_Number=STM32WBA65RIV7, Package=VFQFPN68
X1: library part MCD-02579, "Crystal, 32.768kHz, 6pF, +/-20ppm, 70KR, 1.6x1mm", Manufacturer=NDK, Manufacturer_Part_Number=NX1610SE-32.768KHZ-EXS00A-MU01501, Package=1.6x1mm
X2: library part MCD-02578, "Crystal, 32MHz, 8pF, +/-10ppm, 40R, 1612(metric), T=0.3mm", Manufacturer=NDK, Manufacturer_Part_Number=NX1612SA-32MHZ-EXS00A-CS09166, Package=1612(metric)

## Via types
v1: diameter 0.55, hole 0.35, Top Layer to Bottom Layer, tented both sides, 425 vias
v2: diameter 0.55, hole 0.3, Top Layer to Bottom Layer, tented both sides, 8 vias

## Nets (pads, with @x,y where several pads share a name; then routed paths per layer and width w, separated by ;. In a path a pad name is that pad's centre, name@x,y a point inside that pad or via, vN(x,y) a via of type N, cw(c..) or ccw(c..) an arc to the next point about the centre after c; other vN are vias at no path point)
ant_in: ANT1.1 C1.2 L1.2 | length 1.6
  Top Layer w0.5: L1.2@17.78,42.462 17.78,42.717 17.793,42.73 17.793,43.226 C1.2@17.798,43.231 17.798,43.256 17.789,43.265 ANT1.1@17.789,44.066
ant_path: C2.1 L1.1 R2.1 | length 3.9
  Top Layer w0.5: R2.1@17.765,37.601 C2.1@17.765,40.806 ; C2.1@17.773,40.818 L1.1@17.773,41.554
BOOT0: CN1.9 R4.1 U2.49 | length 26.5
  Top Layer w0.12: v1(8.357,29.337) 8.865,29.845 v1(8.865,33.163) ; U2.49@20.714,31.405 v1(20.714,32.534) 20.714,33.198 R4.1@20.722,33.205
  Bottom Layer w0.12: CN1.9@2.331,28.708 4.099,28.708 4.727,29.337 v1(8.357,29.337) ; v1(8.865,33.163) 14.836,33.163 15.27,32.728 15.27,32.043 16.416,30.897 19.906,30.897 20.714,31.705 v1(20.714,32.534)
ETM.CLK: R5.2 R10.2 U2.36 | length 60.5
  Top Layer w0.1: R10.2@22.708,10.153 R5.2@22.708,11.92 ; U2.36@25.914,31.405 25.914,32.224 26.318,32.628 27.005,32.628 27.911,33.534 27.911,33.536 28.963,34.588 33.596,34.588 34.442,33.743 35.386,33.743 41.956,27.172 41.956,11.087 39.177,8.307 31.026,8.307 v1(30.824,8.105)
  Bottom Layer w0.1: v1(22.71,11.229) 25.834,8.105 v1(30.824,8.105)
ETM.D0: R6.2 R11.2 U2.35 | length 57.9
  Top Layer w0.1: R11.2@23.978,10.153 R6.2@23.978,11.92 ; U2.35@26.314,31.405 26.314,32.2 26.442,32.328 27.129,32.328 28.211,33.41 28.211,33.412 29.087,34.288 33.472,34.288 34.317,33.443 35.262,33.443 41.656,27.048 41.656,11.212 39.052,8.607 30.303,8.607 v1(30.298,8.603)
  Bottom Layer w0.1: v1(23.98,11.229) 23.98,10.383 25.76,8.603 v1(30.298,8.603)
ETM.D1: R7.2 R12.2 U2.34 | length 58.6
  Top Layer w0.1: R12.2@25.273,10.153 R7.2@25.273,11.92 ; U2.34@26.939,30.78 27.164,30.78 27.102,30.842 27.102,31.876 28.511,33.285 28.511,33.287 29.212,33.988 33.348,33.988 34.193,33.143 35.138,33.143 41.356,26.924 41.356,11.336 38.928,8.907 31.098,8.907 30.868,9.137 v1(30.861,9.13)
  Bottom Layer w0.1: v1(25.275,11.229) 25.576,10.928 25.894,10.61 cw(c25.753,10.469) 25.894,10.327 25.471,9.904 ccw(c25.612,9.762) 25.471,9.621 ccw(c25.612,9.762) 25.754,9.621 26.337,10.204 cw(c26.478,10.062) 26.619,10.204 cw(c26.478,10.062) 26.619,9.921 26.036,9.338 ccw(c26.178,9.197) 26.036,9.055 ccw(c26.178,9.197) 26.319,9.055 26.743,9.479 cw(c26.884,9.337) 27.026,9.479 27.24,9.265 27.375,9.13 v1(30.861,9.13)
ETM.D2: R8.2 R13.2 U2.33 | length 58.7
  Top Layer w0.1: R13.2@26.543,10.153 R8.2@26.543,11.92 ; U2.33@26.939,30.38 27.33,30.38 27.61,30.66 27.61,31.96 28.811,33.161 28.811,33.163 29.336,33.688 33.224,33.688 34.069,32.843 35.013,32.843 41.056,26.8 41.056,11.46 38.804,9.207 38.382,9.207 37.797,9.207 cw(c37.797,9.407) 37.597,9.407 37.597,9.621 ccw(c37.397,9.621) 37.197,9.621 37.197,9.407 cw(c36.997,9.407) 36.797,9.407 36.797,9.621 ccw(c36.597,9.621) 36.397,9.621 36.397,9.407 cw(c36.197,9.407) 35.997,9.407 35.997,9.621 ccw(c35.797,9.621) 35.597,9.621 35.597,9.407 cw(c35.397,9.407) 35.197,9.407 35.197,9.621 ccw(c34.997,9.621) 34.797,9.621 34.797,9.407 cw(c34.597,9.407) 34.397,9.407 34.397,9.621 ccw(c34.197,9.621) 33.997,9.621 33.997,9.407 cw(c33.797,9.407) 33.597,9.407 33.597,9.621 ccw(c33.397,9.621) 33.197,9.621 33.197,9.407 cw(c32.997,9.407) 32.797,9.407 32.797,9.621 ccw(c32.597,9.621) 32.397,9.621 32.397,9.407 cw(c32.197,9.407) 32.197,9.207 32.147,9.207 31.483,9.207 v1(30.861,9.83)
  Bottom Layer w0.1: v1(26.545,11.229) 27.945,9.83 v1(30.861,9.83)
ETM.D3: R9.2 R14.2 U2.37 | length 58.6
  Top Layer w0.1: U2.37@25.514,31.405 25.514,32.248 26.194,32.928 26.881,32.928 27.611,33.658 27.611,33.66 28.839,34.888 33.721,34.888 34.566,34.043 35.51,34.043 42.256,27.297 42.256,10.963 39.301,8.007 31.688,8.007 31.319,7.638 31.029,7.638 31.021,7.63 30.257,7.63 29.797,8.09 v1(29.797,10.408) ; R14.2@27.813,10.153 R9.2@27.813,11.92
  Bottom Layer w0.1: v1(27.815,11.229) 28.636,10.408 v1(29.797,10.408)
ETM.JTDI: CN2.22 CN4.8 SB7.1 | length 65.6
  Top Layer w0.1: v1(20.193,13.081) 20.193,6.617 CN4.8@20.196,6.614
  Top Layer w0.12: v1(10.299,27.961) 10.299,19.556 11.547,18.308 11.547,16.324 11.319,16.096 11.319,15.158 11.659,14.819 v1(11.659,11.303)
  Bottom Layer w0.12: SB7.1@9.456,28.931 9.456,28.318 9.812,27.961 v1(10.299,27.961) ; v1(11.659,11.303) 13.229,12.873 14.736,12.873 15.124,13.261 17.7,13.261 17.878,13.083 20.19,13.083 v1(20.193,13.081) 21.15,13.081 ; 21.151,13.08 31.656,13.08 32.703,14.127 42.142,14.127 42.296,14.281 42.296,20.508 41.716,21.088 CN2.22@40.691,21.088
ETM.SWCLK: CN1.15 CN4.4 U2.41 | length 64.5
  Top Layer w0.12: v1(6.297,35.687) 6.297,31.164 3.461,28.329 3.461,25.628 v1(4.191,24.898) 6.414,22.675 6.414,20.601 10.35,16.665 10.35,14.263 10.543,14.069 10.543,10.594 10.35,10.4 v1(10.35,9.246) ; v1(17.653,9.246) 17.653,6.617 CN4.4@17.656,6.614 ; U2.41@23.914,31.405 23.914,32.779 24.359,33.224 v1(24.359,34.102)
  Bottom Layer w0.12: CN1.15@2.331,24.898 v1(4.191,24.898) ; v1(6.297,35.687) 6.309,35.675 11.952,35.675 13.326,34.302 15.299,34.302 15.565,34.036 19.126,34.036 19.507,33.655 21.311,33.655 21.895,34.238 23.541,34.238 23.677,34.102 v1(24.359,34.102) ; v1(10.35,9.246) v1(17.653,9.246)
ETM.SWDIO: CN1.13 CN4.2 U2.42 | length 63.4
  Top Layer w0.12: v1(6.782,36.398) 6.782,31.267 3.731,28.217 3.731,27.053 v1(4.191,26.594) 4.138,26.541 4.138,25.694 6.684,23.148 6.684,20.713 10.62,16.777 10.62,14.452 10.835,14.237 10.835,6.615 v1(10.846,6.604) ; v1(15.398,6.614) CN4.2@16.386,6.614 ; U2.42@23.514,31.405 23.514,32.785 23.863,33.134 23.863,34.536 v1(23.678,34.722)
  Bottom Layer w0.12: CN1.13@2.331,26.168 2.435,26.272 3.869,26.272 v1(4.191,26.594) ; v1(6.782,36.398) 7.235,35.945 12.064,35.945 13.437,34.572 15.411,34.572 15.677,34.306 19.238,34.306 19.619,33.925 21.199,33.925 21.801,34.526 23.061,34.526 23.257,34.722 v1(23.678,34.722) ; v1(10.846,6.604) 10.851,6.609 15.393,6.609 v1(15.398,6.614)
ETM.SWO: CN2.12 CN4.6 U2.39 | length 73.8
  Top Layer w0.1: v1(18.923,12.598) 18.923,6.617 CN4.6@18.926,6.614 ; v1(32.817,12.294) 33.462,12.939 33.462,17.986 36.566,21.09 38.834,21.09 39.716,21.972 39.716,26.245 36.497,29.464 v1(33.782,29.464)
  Top Layer w0.12: U2.39@24.714,31.405 24.714,32.766 25.4,33.452 v1(25.4,34.9)
  Bottom Layer w0.1: v1(18.923,12.598) 18.93,12.606 20.953,12.606 21.347,12.605 ; 21.348,12.606 21.459,12.606 21.674,12.82 31.811,12.82 32.342,12.289 32.812,12.289 v1(32.817,12.294) ; v1(25.4,34.9) 27.598,34.9 28.031,34.466 28.031,33.364 29.08,32.316 32.818,32.316 33.045,32.088 33.045,31.275 33.795,30.525 33.795,29.477 v1(33.782,29.464) 33.795,29.451 33.795,29.046 32.154,27.405 32.154,27.07 32.455,26.769 32.715,26.769 32.715,26.772 38.287,26.772 38.954,27.438 CN2.12@40.691,27.438
GND: C1.1 C2.2 C3.1 C4.1 C5.1 C6.2 C7.2 C8.2 C9.2 C10.1 C11.2 C12.1 C13.2 C14.2 C15.2 C16.1 C17.2 C18.2 C19.2 C20.1 C21.1 C22.1 C23.2 C24.2 C25.1 C26.1 C27.1 C28.1 C29.1 C30.1 C31.1 C32.1 CN1.1 CN1.6 CN1.7 CN1.14 CN1.17 CN1.22 CN1.25 CN1.28 CN1.31 CN1.34 CN1.37 CN1.40 CN1.46 CN1.49 CN2.2 CN2.8 CN2.14 CN2.20 CN2.26 CN2.32 CN2.38 CN2.44 CN2.50 CN3.2 CN3.3 CN3.4 CN3.5 CN4.3 CN4.5 CN4.9 CN4.15 CN4.17 CN4.19 R4.2 SB17.1 SC1.1 SC2.1 SC3.1 SC4.1 SC5.1 U1.A2 U1.B1 U1.B2 U1.B3 U2.1 U2.69 X2.2 X2.4 | length 87.2
  Top Layer w0.2: v1(13.894,24.768) 14.514,24.768 C16.1@14.536,24.79 ; v1(13.895,25.603) C15.2@14.536,25.603 ; v1(13.97,31.589) 13.979,31.598 C9.2@14.815,31.598 ; v1(14.173,30.48) C11.2@14.815,30.48 ; X2.4@15.816,28.606 15.899,28.689 15.937,28.651 16.548,28.651 v1(16.548,28.664) ; v1(17.22,29.691) 17.221,29.693 17.221,29.718 16.993,29.947 14.173,29.947 14.021,29.794 v1(14.021,29.362) 14.021,27.904 v1(14.576,27.349) v1(16.262,27.348) 16.604,27.348 v1(17.424,28.169) ; C17.2@19.322,22.86 v1(19.322,23.505) 19.572,23.755 U2.1@19.914,23.755 ; v1(19.71,34.722) 19.759,34.673 19.759,34.153 C6.2@19.807,34.105 ; R4.2@20.722,34.105 v1(20.722,34.722) ; C19.2@26.391,21.089 26.416,21.089 26.692,20.813 26.692,20.552 v1(26.759,20.485) ; C7.2@26.891,33.757 v1(26.891,34.361) ; C18.2@28.296,21.318 28.927,21.318 v1(28.933,21.324) ; v1(28.651,29.362) 28.651,29.625 29.552,30.526 29.552,31.195 29.744,31.387 31.249,31.387 31.42,31.217 v1(31.42,30.505) v1(31.42,29.458) v1(31.42,28.038) 31.353,27.971 31.353,27.556 30.772,26.975 v1(29.642,26.975) ; v1(30.302,24.867) C14.2@30.302,25.458 ; C8.2@30.498,32.156 v1(30.498,32.835)
  Top Layer w0.3: C23.2@18.179,19.507 v1(18.974,19.507) C20.1@18.974,20.509 ; v1@21.463,4.496 21.466,4.493 CN4.9@21.466,2.544 ; v1(23.343,19.685) C21.1@23.343,20.327 ; v1(24.257,19.685) C22.1@24.257,20.327
  Bottom Layer w0.2: v1(38.506,22.352) 40.685,22.352 CN2.20@40.691,22.358 ; v1(38.729,3.308) CN2.50@40.691,3.308 ; v1(38.729,7.118) CN2.44@40.691,7.118 ; v1(38.729,14.738) CN2.32@40.691,14.738 ; v1(38.729,18.548) CN2.26@40.691,18.548 ; v1(38.811,33.796) 38.818,33.788 CN2.2@40.691,33.788 ; CN2.38@40.691,10.928 41.716,10.928 42.426,10.219 v1(42.426,9.014) ; CN2.14@40.691,26.168 41.716,26.168 42.425,26.877 v1(42.425,28.065) ; CN2.8@40.691,29.978 40.71,29.997 v1(42.425,29.997)
  Bottom Layer w0.3: CN1.25@2.319,18.548 4.247,18.548 v1(4.255,18.556) ; CN1.49@2.331,3.308 4.26,3.308 v1(4.267,3.316) ; CN1.37@2.331,10.928 4.26,10.928 v1(4.267,10.936) ; CN1.31@2.331,14.738 v1@4.26,14.738 ; CN1.17@2.331,23.628 4.26,23.628 v1(4.267,23.636) ; CN1.7@2.331,29.978 4.26,29.978 v1(4.267,29.986) ; CN1.1@2.331,33.788 2.506,33.963 4.219,33.963 v1(4.267,34.011) ; v1@4.473,13.468 CN1.34@6.401,13.468 ; v1(4.623,25.984) 4.671,26.032 6.265,26.032 CN1.14@6.401,26.168 ; CN1.46@6.401,5.848 8.33,5.848 v1(8.337,5.856) ; CN1.40@6.401,9.658 8.33,9.658 v1(8.337,9.666) ; CN1.28@6.401,17.278 6.598,17.475 v1(8.458,17.475) C29.1@8.458,16.808 ; CN1.22@6.401,21.088 8.33,21.088 v1(8.337,21.096) ; CN1.6@6.401,31.248 8.33,31.248 v1(8.337,31.256) ; v2(8.458,13.081) C30.1@8.458,13.825 ; C28.1@10.458,22.352 v1(11.113,22.352) ; C27.1@10.457,23.627 v1(11.113,23.627) ; C32.1@10.458,3.306 11.275,3.306 v2(11.278,3.308) ; C26.1@10.469,33.832 v1(11.202,33.832) ; v1(21.456,4.489) 21.456,5.37 SB17.1@21.673,5.588 ; v1(31.978,3.327) C31.1@32.685,3.327
  other v1: 2.547,0.625 4.547,0.625 6.547,0.625 8.547,0.625 10.547,0.625 12.547,0.625 14.547,0.625 16.547,0.625 18.547,0.625 20.547,0.625 22.547,0.625 24.547,0.625 26.547,0.625 28.547,0.625 30.547,0.625 32.547,0.625 34.547,0.625 36.547,0.625 38.547,0.625 40.547,0.625 13.644,2.495 0.584,3.835 42.418,3.835 8.547,4.625 10.547,4.625 12.547,4.625 16.547,4.625 18.547,4.625 20.547,4.625 24.547,4.625 26.547,4.625 28.547,4.625 9.547,6.625 42.418,7.62 4.547,8.625 16.547,8.625 13.538,10.287 21.547,10.625 0.584,11.455 15.705,12.776 4.466,13.461 23.368,13.868 28.956,14.199 4.267,14.746 0.584,15.24 27.402,15.232 28.955,15.685 19.708,17.056 27.229,17.501 17.6,18.727 15.191,18.903 0.584,18.999 31.801,20.472 33.782,21.417 32.309,21.92 12.769,22.104 30.15,22.276 34.544,22.581 33.757,23.647 0.584,24.13 28.977,24.196 34.798,24.232 8.547,24.625 20.714,25.18 21.914,25.18 23.114,25.18 24.314,25.18 25.514,25.18 38.556,25.826 12.522,25.933 20.714,26.38 21.914,26.38 23.114,26.38 24.314,26.38 25.514,26.38 20.714,27.58 21.914,27.58 23.114,27.58 24.314,27.58 25.514,27.58 33.553,27.864 11.024,28.327 20.714,28.78 21.914,28.78 23.114,28.78 24.314,28.78 25.514,28.78 20.714,29.98 21.914,29.98 23.114,29.98 24.314,29.98 25.514,29.98 0.584,30.48 18.847,31.521 33.553,31.572 11.665,31.607 9.495,31.655 16.695,31.8 18.588,32.633 38.547,32.625 42.418,33.274 16.883,33.452 18.517,33.528 12.313,34.51 5.547,34.625 37.547,34.625 16.866,34.798 18.618,34.798 35.968,34.864 39.032,34.864 41.576,34.864 0.818,35.171 42.367,35.663 16.869,35.837 18.658,35.831 19.672,35.839 38.06,35.816 20.745,35.851 21.741,36.207 33.648,36.3 2.547,36.625 4.547,36.625 8.547,36.625 10.547,36.625 14.547,36.625 32.547,36.625 38.547,36.625 22.799,36.769 42.367,36.916 16.858,36.937 32.14,37.359 33.02,37.356 29.515,37.541 23.478,37.555 19.527,37.61 20.326,37.601 18.667,37.743 16.316,37.76 21.26,37.995 24.278,38.07 30.29,38.11 42.367,38.117 25.4,38.139 26.564,38.139 27.729,38.139 28.765,38.129 31.319,38.139 18.708,38.499 3.547,38.625 5.547,38.625 7.547,38.625 9.547,38.625 11.547,38.625 13.547,38.625 19.547,38.625 37.547,38.625 39.547,38.625 16.205,38.725 22.189,38.764 41.148,39.014 16.883,39.239 18.708,39.324 42.367,39.425 23.239,39.578 24.359,39.863 25.478,39.863 26.538,39.863 27.729,39.863 28.787,39.863 29.946,39.863 30.919,39.863 31.869,39.863 32.926,39.863 16.987,40.1 18.542,40.123 33.301,40.594 2.547,40.625 4.547,40.625 6.547,40.625 8.547,40.625 10.547,40.625 12.547,40.625 14.547,40.625 20.547,40.625 22.547,40.625 24.547,40.625 26.547,40.625 28.547,40.625 30.547,40.625 32.547,40.625 36.547,40.625 38.547,40.625 42.367,40.637 16.205,40.765 18.542,41.083 16.951,41.514 33.314,41.514 18.542,41.957 37.358,42.16 42.367,42.164 16.858,42.455 7.547,42.625 9.547,42.625 11.547,42.625 13.547,42.625 15.547,42.625 18.592,42.642 19.547,42.625 21.547,42.625 23.547,42.625 25.547,42.625 27.547,42.625 29.547,42.625 31.547,42.625 39.547,42.625 41.547,42.625 33.301,42.814 16.161,43.314 34.912,43.314 36.699,43.314 38.271,43.314 39.726,43.314 41.196,43.314 18.592,43.46
GPIO2: CN1.8 SB4.1 | length 3
  Bottom Layer w0.12: CN1.8@6.401,29.978 6.42,29.997 SB4.1@9.367,29.997
GPIO8: CN1.19 R6.1 | length 30.3
  Top Layer w0.12: v1(4.267,22.366) 10.058,16.574 v1(10.058,13.868) ; v1(23.975,15.542) 23.975,12.823 R6.1@23.978,12.82
  Bottom Layer w0.12: CN1.19@2.331,22.358 v1@4.26,22.358 ; v1(10.058,13.868) 11.879,13.868 13.469,15.459 20.604,15.459 20.912,15.767 21.831,15.767 22.055,15.542 v1(23.975,15.542) v1@23.978,15.545
GPIO9: CN1.21 R7.1 | length 30.9
  Top Layer w0.12: v1(4.267,21.096) 5.799,19.564 5.799,16.982 v1(9.442,13.338) ; R7.1@25.273,12.82 v1(25.273,15.061)
  Bottom Layer w0.12: CN1.21@2.331,21.088 v1@4.26,21.088 ; v1(9.442,13.338) 9.456,13.352 11.751,13.352 12.02,13.621 12.02,13.628 13.581,15.189 20.715,15.189 20.928,15.401 21.814,15.401 22.159,15.057 25.269,15.057 v1(25.273,15.061)
GPIO10: CN1.23 R8.1 | length 32.6
  Top Layer w0.12: v1(4.267,19.826) 5.371,18.722 5.371,15.28 8.291,12.36 9.617,12.36 v1(10.058,12.802) ; v1(26.536,14.576) 26.536,12.827 R8.1@26.543,12.82
  Bottom Layer w0.12: CN1.23@2.331,19.818 v1@4.26,19.818 ; v1(10.058,12.802) 11.583,12.802 12.29,13.509 12.29,13.516 13.693,14.919 20.861,14.919 21.074,15.131 21.702,15.131 22.457,14.376 26.251,14.376 26.45,14.576 v1(26.536,14.576)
